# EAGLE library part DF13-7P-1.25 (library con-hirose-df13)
DF13-7P 1.25mm Pitch Miniature Crimping Connector.
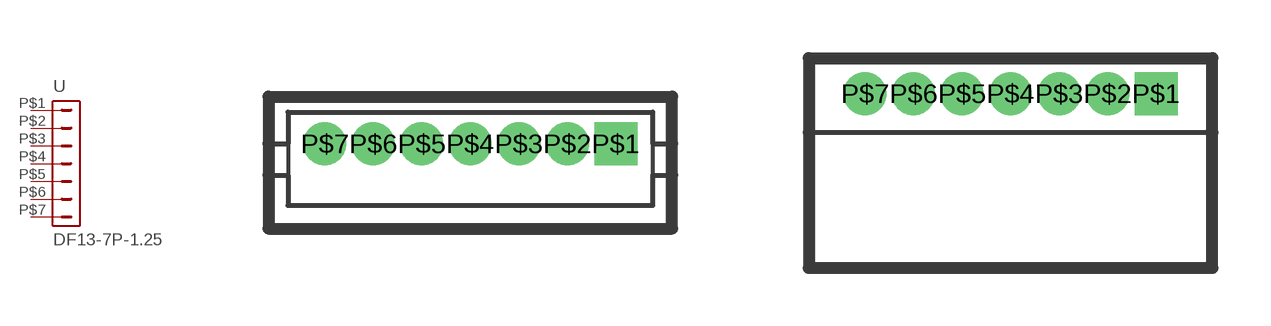
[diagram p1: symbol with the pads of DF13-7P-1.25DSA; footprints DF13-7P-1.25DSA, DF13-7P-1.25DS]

Designator prefix -

## DF13-7P-1.25DSA  [DF13-7P-1.25DSA]
P$1  1  pas
P$2  2  pas
P$3  3  pas
P$4  4  pas
P$5  5  pas
P$6  6  pas
P$7  7  pas

## DF13-7P-1.25DS  [DF13-7P-1.25DS]
Pads as for DF13-7P-1.25DSA

## DF13-7P-1.25V  [DF13C-7P-1.25V]
Pads as for DF13-7P-1.25DSA

## DF13-7P-1.25H  [DF13A-7P-1.25H]
Pads as for DF13-7P-1.25DSA

## Footprint DF13-7P-1.25DSA (pad centres in mm)
Single Row Straight Pin Header (Through hole)
drill 0.6 pad 1.016 square: P$1 3.75,0
drill 0.6 pad 1.016 round: P$2 2.5,0; P$3 1.25,0; P$4 0,0; P$5 -1.25,0; P$6 -2.5,0; P$7 -3.75,0

## Footprint DF13-7P-1.25DS (pad centres in mm)
Single Row Right Angle Pin Header (Through hole)
drill 0.6 pad 1.016 square: P$1 3.75,0
drill 0.6 pad 1.016 round: P$2 2.5,0; P$3 1.25,0; P$4 0,0; P$5 -1.25,0; P$6 -2.5,0; P$7 -3.75,0

## Footprint DF13C-7P-1.25V (pad centres in mm)
Single Row Straight Pin Header (SMT)
smd 1.6 x 2.2: M$0 6.2,-1.8; M$1 -6.2,-1.8
smd 0.7 x 1.8: P$1 -3.75,0.9; P$2 -2.5,0.9; P$3 -1.25,0.9; P$4 0,0.9; P$5 1.25,0.9; P$6 2.5,0.9; P$7 3.75,0.9

## Footprint DF13A-7P-1.25H (pad centres in mm)
Single Row Straight Pin Header (SMT)
smd 1.6 x 2.2: M$0 -6.1,2.4; M$1 6.1,2.4
smd 0.7 x 1.8: P$1 -3.75,-0.9; P$2 -2.5,-0.9; P$3 -1.25,-0.9; P$4 0,-0.9; P$5 1.25,-0.9; P$6 2.5,-0.9; P$7 3.75,-0.9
